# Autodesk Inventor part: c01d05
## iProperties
Created: 2004-05
Part Number: c01d05
Document SubType Name: Modeling
Designer: CADCIM Technologies
Manufacturer: Standard
Standards Organization: Custom
Author: CADCIM Technologies
